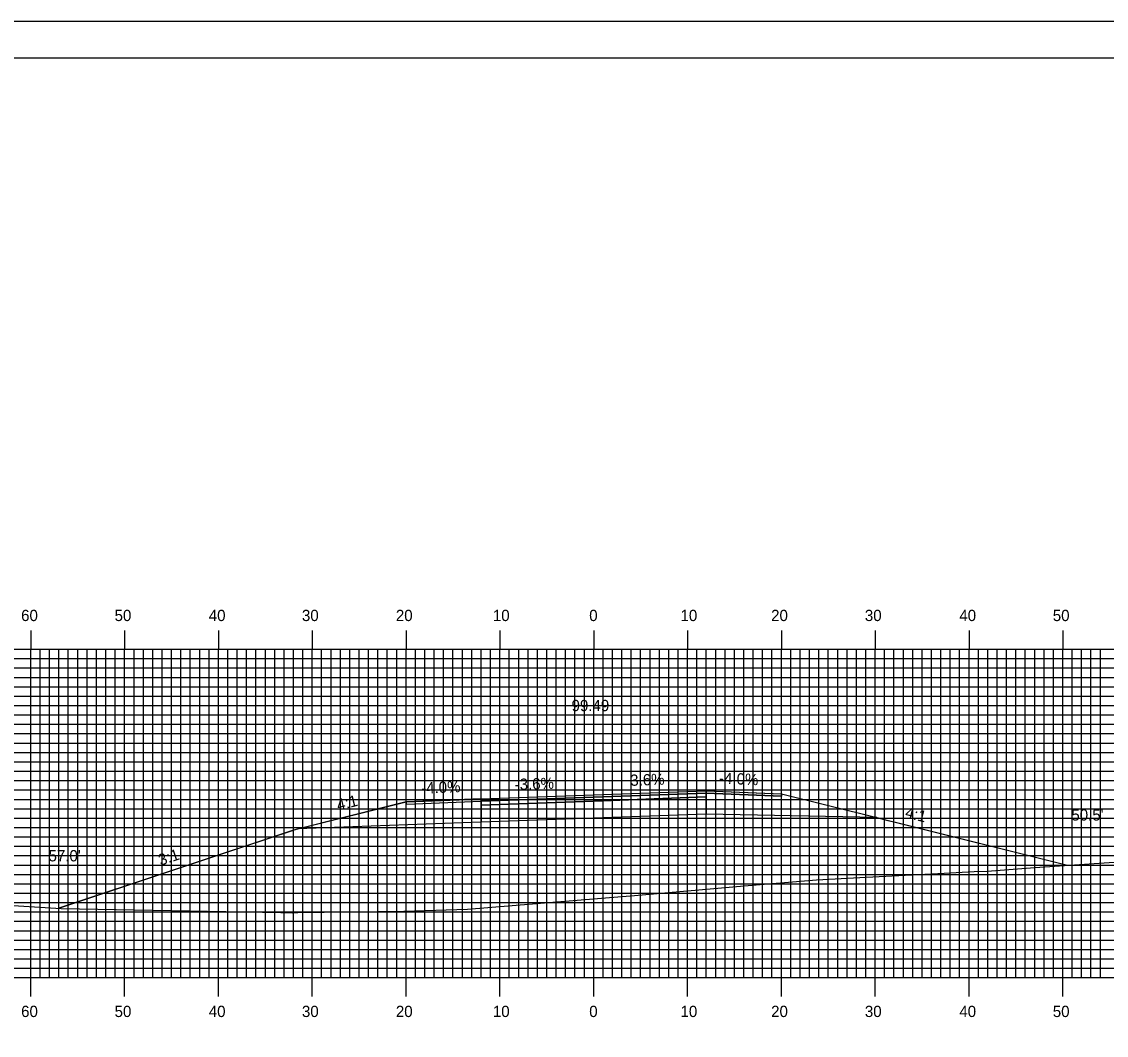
# Model space of a CAD drawing. Extents: x 1762972 to 1763315, y 442591 to 442811.
# Drawn here: x 1763076.3 to 1763191.9, y 442702.5 to 442810.5 of the extents above; entities that cross this region are included whole.
import ezdxf

# ---------------------------------------------------------------- set-up
doc = ezdxf.new("R2010")
doc.units = 0
for name, color, linetype in [('ANNOTATION', 7, 'Continuous'), ('BORDER', 7, 'Continuous'), ('D_Roadway_Centerline', 7, 'Continuous'), ('D_Roadway_Centerline_Text', 7, 'Continuous'), ('D_Roadway_Edge_Shoulder', 7, 'Continuous'), ('D_Roadway_Edge_TW', 7, 'Continuous'), ('D_Roadway_Pavement', 7, 'Continuous'), ('D_Roadway_SlopeLines', 7, 'Continuous'), ('D_Roadway_SubGrade', 7, 'Continuous'), ('D_Text_Standard', 7, 'Continuous'), ('H_V ANNOTATION', 7, 'Continuous'), ('MAJOR', 7, 'Continuous'), ('MINOR', 7, 'Continuous'), ('PLOT BOUNDARY', 7, 'Continuous'), ('S_Roadway_Centerline', 7, 'Continuous')]:
    doc.layers.add(name, color=color, linetype=linetype)

msp = doc.modelspace()

# ---------------------------------------------------------------- linework, layer by layer
at = {"layer": 'BORDER'}
msp.add_lwpolyline([(1762987.69, 442596.67), (1763307.69, 442596.67), (1763307.69, 442806.67), (1762987.69, 442806.67)], close=True, dxfattribs=at)
at = {"layer": 'D_Roadway_Centerline'}
msp.add_lwpolyline([(1763080.27, 442716.06), (1763100.01, 442722.64), (1763105.29, 442724.4), (1763105.35, 442724.42), (1763105.76, 442724.52), (1763112.1, 442726.11), (1763117.29, 442727.4), (1763122.93, 442727.63), (1763125.29, 442727.72), (1763125.29, 442727.72), (1763131.29, 442727.94), (1763137.29, 442728.16), (1763149.29, 442728.59), (1763149.29, 442728.59), (1763149.3, 442728.59), (1763156.38, 442728.3), (1763157.29, 442728.27), (1763167.47, 442725.72), (1763168.65, 442725.43), (1763169.29, 442725.27), (1763169.3, 442725.27), (1763187.78, 442720.65)], dxfattribs=at)
at = {"layer": 'D_Roadway_Edge_Shoulder'}
for points in [[(1763149.29, 442728.59), (1763157.29, 442728.27), (1763157.29, 442728.02), (1763149.29, 442728.34)], [(1763125.29, 442727.72), (1763117.29, 442727.4), (1763117.29, 442727.15), (1763125.29, 442727.47)]]:
    msp.add_lwpolyline(points, close=True, dxfattribs=at)
at = {"layer": 'D_Roadway_Edge_TW'}
for points in [[(1763125.29, 442727.47), (1763125.29, 442727.72), (1763137.29, 442728.16), (1763149.29, 442728.59), (1763149.29, 442728.34), (1763137.29, 442727.91)], [(1763149.29, 442728.59), (1763149.29, 442728.59), (1763149.29, 442728.34), (1763149.29, 442728.34)]]:
    msp.add_lwpolyline(points, close=True, dxfattribs=at)
at = {"layer": 'D_Roadway_Pavement'}
for points in [[(1763125.29, 442727.06), (1763125.29, 442727.47), (1763137.29, 442727.91), (1763149.29, 442728.34), (1763149.29, 442727.92), (1763137.29, 442727.49)], [(1763149.29, 442728.34), (1763149.29, 442728.34), (1763149.29, 442727.92), (1763149.29, 442727.92)]]:
    msp.add_lwpolyline(points, close=True, dxfattribs=at)
msp.add_lwpolyline([(1763149.29, 442728.34), (1763149.29, 442727.92)], dxfattribs=at)
msp.add_lwpolyline([(1763149.29, 442728.34), (1763149.29, 442727.92)], dxfattribs=at)
msp.add_lwpolyline([(1763149.29, 442728.34), (1763149.29, 442727.92)], dxfattribs=at)
at = {"layer": 'D_Roadway_SlopeLines'}
for points in [[(1763117.29, 442727.4), (1763105.29, 442724.4), (1763080.27, 442716.06)], [(1763157.29, 442728.27), (1763167.47, 442725.72), (1763169.29, 442725.27), (1763187.78, 442720.65)]]:
    msp.add_lwpolyline(points, dxfattribs=at)
at = {"layer": 'D_Roadway_SubGrade'}
for points in [[(1763117.29, 442727.15), (1763125.29, 442727.47), (1763125.29, 442727.06), (1763125.29, 442725.22), (1763105.76, 442724.52), (1763117.29, 442727.4)], [(1763125.29, 442725.22), (1763125.29, 442727.06), (1763137.29, 442727.49), (1763149.29, 442727.92), (1763149.29, 442726.09), (1763137.29, 442725.66)], [(1763149.29, 442727.92), (1763149.29, 442728.34), (1763157.29, 442728.02), (1763157.29, 442728.27), (1763167.47, 442725.72), (1763149.29, 442726.09)], [(1763149.29, 442727.92), (1763149.29, 442727.92), (1763149.29, 442726.09), (1763149.29, 442726.09)]]:
    msp.add_lwpolyline(points, close=True, dxfattribs=at)
at = {"layer": 'MAJOR'}
for p, q in [((1763077.29, 442745.67), (1763077.29, 442743.67)), ((1763087.29, 442745.67), (1763087.29, 442743.67)), ((1763097.29, 442745.67), (1763097.29, 442743.67)), ((1763107.29, 442745.67), (1763107.29, 442743.67)), ((1763117.29, 442745.67), (1763117.29, 442743.67)), ((1763127.29, 442745.67), (1763127.29, 442743.67)), ((1763137.29, 442745.67), (1763137.29, 442743.67)), ((1763147.29, 442745.67), (1763147.29, 442743.67)), ((1763157.29, 442745.67), (1763157.29, 442743.67)), ((1763167.29, 442745.67), (1763167.29, 442743.67)), ((1763177.29, 442745.67), (1763177.29, 442743.67)), ((1763187.29, 442745.67), (1763187.29, 442743.67)), ((1762997.29, 442743.67), (1763277.29, 442743.67)), ((1762997.29, 442743.67), (1763277.29, 442743.67)), ((1763077.29, 442708.67), (1763077.29, 442743.67)), ((1763087.29, 442708.67), (1763087.29, 442743.67)), ((1763097.29, 442708.67), (1763097.29, 442743.67)), ((1763107.29, 442708.67), (1763107.29, 442743.67)), ((1763117.29, 442708.67), (1763117.29, 442743.67)), ((1763127.29, 442708.67), (1763127.29, 442743.67)), ((1763137.29, 442708.67), (1763137.29, 442743.67)), ((1763147.29, 442708.67), (1763147.29, 442743.67)), ((1763157.29, 442708.67), (1763157.29, 442743.67)), ((1763167.29, 442708.67), (1763167.29, 442743.67)), ((1763177.29, 442708.67), (1763177.29, 442743.67)), ((1763187.29, 442708.67), (1763187.29, 442743.67)), ((1762997.29, 442738.67), (1763277.29, 442738.67)), ((1762997.29, 442733.67), (1763277.29, 442733.67)), ((1762997.29, 442728.67), (1763277.29, 442728.67)), ((1762997.29, 442723.67), (1763277.29, 442723.67)), ((1762997.29, 442718.67), (1763277.29, 442718.67)), ((1762997.29, 442713.67), (1763277.29, 442713.67)), ((1762997.29, 442708.67), (1763277.29, 442708.67)), ((1762997.29, 442708.67), (1763277.29, 442708.67)), ((1763077.29, 442706.66), (1763077.29, 442708.67)), ((1763087.29, 442706.66), (1763087.29, 442708.67)), ((1763097.29, 442706.66), (1763097.29, 442708.67)), ((1763107.29, 442706.66), (1763107.29, 442708.67)), ((1763117.29, 442706.66), (1763117.29, 442708.67)), ((1763127.29, 442706.66), (1763127.29, 442708.67)), ((1763137.29, 442706.66), (1763137.29, 442708.67)), ((1763147.29, 442706.66), (1763147.29, 442708.67)), ((1763157.29, 442706.66), (1763157.29, 442708.67)), ((1763167.29, 442706.66), (1763167.29, 442708.67)), ((1763177.29, 442706.66), (1763177.29, 442708.67)), ((1763187.29, 442706.66), (1763187.29, 442708.67))]:
    msp.add_line(p, q, dxfattribs=at)
at = {"layer": 'MINOR'}
for p, q in [((1763078.29, 442708.67), (1763078.29, 442743.67)), ((1763079.29, 442708.67), (1763079.29, 442743.67)), ((1763080.29, 442708.67), (1763080.29, 442743.67)), ((1763081.29, 442708.67), (1763081.29, 442743.67)), ((1763082.29, 442708.67), (1763082.29, 442743.67)), ((1763083.29, 442708.67), (1763083.29, 442743.67)), ((1763084.29, 442708.67), (1763084.29, 442743.67)), ((1763085.29, 442708.67), (1763085.29, 442743.67)), ((1763086.29, 442708.67), (1763086.29, 442743.67)), ((1763088.29, 442708.67), (1763088.29, 442743.67)), ((1763089.29, 442708.67), (1763089.29, 442743.67)), ((1763090.29, 442708.67), (1763090.29, 442743.67)), ((1763091.29, 442708.67), (1763091.29, 442743.67)), ((1763092.29, 442708.67), (1763092.29, 442743.67)), ((1763093.29, 442708.67), (1763093.29, 442743.67)), ((1763094.29, 442708.67), (1763094.29, 442743.67)), ((1763095.29, 442708.67), (1763095.29, 442743.67)), ((1763096.29, 442708.67), (1763096.29, 442743.67)), ((1763098.29, 442708.67), (1763098.29, 442743.67)), ((1763099.29, 442708.67), (1763099.29, 442743.67)), ((1763100.29, 442708.67), (1763100.29, 442743.67)), ((1763101.29, 442708.67), (1763101.29, 442743.67)), ((1763102.29, 442708.67), (1763102.29, 442743.67)), ((1763103.29, 442708.67), (1763103.29, 442743.67)), ((1763104.29, 442708.67), (1763104.29, 442743.67)), ((1763105.29, 442708.67), (1763105.29, 442743.67)), ((1763106.29, 442708.67), (1763106.29, 442743.67)), ((1763108.29, 442708.67), (1763108.29, 442743.67)), ((1763109.29, 442708.67), (1763109.29, 442743.67)), ((1763110.29, 442708.67), (1763110.29, 442743.67)), ((1763111.29, 442708.67), (1763111.29, 442743.67)), ((1763112.29, 442708.67), (1763112.29, 442743.67)), ((1763113.29, 442708.67), (1763113.29, 442743.67)), ((1763114.29, 442708.67), (1763114.29, 442743.67)), ((1763115.29, 442708.67), (1763115.29, 442743.67)), ((1763116.29, 442708.67), (1763116.29, 442743.67)), ((1763118.29, 442708.67), (1763118.29, 442743.67)), ((1763119.29, 442708.67), (1763119.29, 442743.67)), ((1763120.29, 442708.67), (1763120.29, 442743.67)), ((1763121.29, 442708.67), (1763121.29, 442743.67)), ((1763122.29, 442708.67), (1763122.29, 442743.67)), ((1763123.29, 442708.67), (1763123.29, 442743.67)), ((1763124.29, 442708.67), (1763124.29, 442743.67)), ((1763125.29, 442708.67), (1763125.29, 442743.67)), ((1763126.29, 442708.67), (1763126.29, 442743.67)), ((1763128.29, 442708.67), (1763128.29, 442743.67)), ((1763129.29, 442708.67), (1763129.29, 442743.67)), ((1763130.29, 442708.67), (1763130.29, 442743.67)), ((1763131.29, 442708.67), (1763131.29, 442743.67)), ((1763132.29, 442708.67), (1763132.29, 442743.67)), ((1763133.29, 442708.67), (1763133.29, 442743.67)), ((1763134.29, 442708.67), (1763134.29, 442743.67)), ((1763135.29, 442708.67), (1763135.29, 442743.67)), ((1763136.29, 442708.67), (1763136.29, 442743.67)), ((1763138.29, 442708.67), (1763138.29, 442743.67)), ((1763139.29, 442708.67), (1763139.29, 442743.67)), ((1763140.29, 442708.67), (1763140.29, 442743.67)), ((1763141.29, 442708.67), (1763141.29, 442743.67)), ((1763142.29, 442708.67), (1763142.29, 442743.67)), ((1763143.29, 442708.67), (1763143.29, 442743.67)), ((1763144.29, 442708.67), (1763144.29, 442743.67)), ((1763145.29, 442708.67), (1763145.29, 442743.67)), ((1763146.29, 442708.67), (1763146.29, 442743.67)), ((1763148.29, 442708.67), (1763148.29, 442743.67)), ((1763149.29, 442708.67), (1763149.29, 442743.67)), ((1763150.29, 442708.67), (1763150.29, 442743.67)), ((1763151.29, 442708.67), (1763151.29, 442743.67)), ((1763152.29, 442708.67), (1763152.29, 442743.67)), ((1763153.29, 442708.67), (1763153.29, 442743.67)), ((1763154.29, 442708.67), (1763154.29, 442743.67)), ((1763155.29, 442708.67), (1763155.29, 442743.67)), ((1763156.29, 442708.67), (1763156.29, 442743.67)), ((1763158.29, 442708.67), (1763158.29, 442743.67)), ((1763159.29, 442708.67), (1763159.29, 442743.67)), ((1763160.29, 442708.67), (1763160.29, 442743.67)), ((1763161.29, 442708.67), (1763161.29, 442743.67)), ((1763162.29, 442708.67), (1763162.29, 442743.67)), ((1763163.29, 442708.67), (1763163.29, 442743.67)), ((1763164.29, 442708.67), (1763164.29, 442743.67)), ((1763165.29, 442708.67), (1763165.29, 442743.67)), ((1763166.29, 442708.67), (1763166.29, 442743.67)), ((1763168.29, 442708.67), (1763168.29, 442743.67)), ((1763169.29, 442708.67), (1763169.29, 442743.67)), ((1763170.29, 442708.67), (1763170.29, 442743.67)), ((1763171.29, 442708.67), (1763171.29, 442743.67)), ((1763172.29, 442708.67), (1763172.29, 442743.67)), ((1763173.29, 442708.67), (1763173.29, 442743.67)), ((1763174.29, 442708.67), (1763174.29, 442743.67)), ((1763175.29, 442708.67), (1763175.29, 442743.67)), ((1763176.29, 442708.67), (1763176.29, 442743.67)), ((1763178.29, 442708.67), (1763178.29, 442743.67)), ((1763179.29, 442708.67), (1763179.29, 442743.67)), ((1763180.29, 442708.67), (1763180.29, 442743.67)), ((1763181.29, 442708.67), (1763181.29, 442743.67)), ((1763182.29, 442708.67), (1763182.29, 442743.67)), ((1763183.29, 442708.67), (1763183.29, 442743.67)), ((1763184.29, 442708.67), (1763184.29, 442743.67)), ((1763185.29, 442708.67), (1763185.29, 442743.67)), ((1763186.29, 442708.67), (1763186.29, 442743.67)), ((1763188.29, 442708.67), (1763188.29, 442743.67)), ((1763189.29, 442708.67), (1763189.29, 442743.67)), ((1763190.29, 442708.67), (1763190.29, 442743.67)), ((1763191.29, 442708.67), (1763191.29, 442743.67)), ((1762997.29, 442742.67), (1763277.29, 442742.67)), ((1762997.29, 442741.67), (1763277.29, 442741.67)), ((1762997.29, 442740.67), (1763277.29, 442740.67)), ((1762997.29, 442739.67), (1763277.29, 442739.67)), ((1762997.29, 442737.67), (1763277.29, 442737.67)), ((1762997.29, 442736.67), (1763277.29, 442736.67)), ((1762997.29, 442735.67), (1763277.29, 442735.67)), ((1762997.29, 442734.67), (1763277.29, 442734.67)), ((1762997.29, 442732.67), (1763277.29, 442732.67)), ((1762997.29, 442731.67), (1763277.29, 442731.67)), ((1762997.29, 442730.67), (1763277.29, 442730.67)), ((1762997.29, 442729.67), (1763277.29, 442729.67)), ((1762997.29, 442727.67), (1763277.29, 442727.67)), ((1762997.29, 442726.67), (1763277.29, 442726.67)), ((1762997.29, 442725.67), (1763277.29, 442725.67)), ((1762997.29, 442724.67), (1763277.29, 442724.67)), ((1762997.29, 442722.67), (1763277.29, 442722.67)), ((1762997.29, 442721.67), (1763277.29, 442721.67)), ((1762997.29, 442720.67), (1763277.29, 442720.67)), ((1762997.29, 442719.67), (1763277.29, 442719.67)), ((1762997.29, 442717.67), (1763277.29, 442717.67)), ((1762997.29, 442716.67), (1763277.29, 442716.67)), ((1762997.29, 442715.67), (1763277.29, 442715.67)), ((1762997.29, 442714.67), (1763277.29, 442714.67)), ((1762997.29, 442712.67), (1763277.29, 442712.67)), ((1762997.29, 442711.67), (1763277.29, 442711.67)), ((1762997.29, 442710.67), (1763277.29, 442710.67)), ((1762997.29, 442709.67), (1763277.29, 442709.67))]:
    msp.add_line(p, q, dxfattribs=at)
at = {"layer": 'PLOT BOUNDARY'}
msp.add_lwpolyline([(1762971.51, 442590.55), (1763311.51, 442590.55), (1763311.51, 442810.55), (1762971.51, 442810.55)], close=True, dxfattribs=at)
at = {"layer": 'S_Roadway_Centerline'}
msp.add_lwpolyline([(1763069.72, 442716.7), (1763080.53, 442716.05), (1763103.93, 442715.62), (1763105.16, 442715.59), (1763105.74, 442715.6), (1763117.05, 442715.77), (1763123.85, 442715.98), (1763140.29, 442717.3), (1763141.65, 442717.41), (1763153.32, 442718.46), (1763161.05, 442719.1), (1763165.67, 442719.34), (1763174.63, 442719.79), (1763177.84, 442719.97), (1763179.24, 442720.02), (1763184.32, 442720.42), (1763198.54, 442721.35)], dxfattribs=at)

# ---------------------------------------------------------------- texts
at = {"layer": 'ANNOTATION'}
for s, rotation, p in [('-4.0%', 2.2904, (1763118.92, 442728.27)), ('-3.6%', 2.0618, (1763128.88, 442728.65)), ('3.6%', 2.0619, (1763141.2, 442729.1)), ('-4.0%', 357.7096, (1763150.63, 442729.34)), ('4:1', 14.0402, (1763110.06, 442726.46)), ('4:1', 345.9626, (1763170.41, 442725.75)), ('3:1', 18.4355, (1763091.12, 442720.59))]:
    msp.add_text(s, height=1.2, rotation=rotation, dxfattribs=at).set_placement(p)
at = {"layer": 'D_Roadway_Centerline'}
for s, p in [('C', (1763137.29, 442728.16)), ('L', (1763137.29, 442728.15))]:
    msp.add_text(s, height=0.0146, dxfattribs=at).set_placement(p)
at = {"layer": 'D_Roadway_Centerline_Text'}
msp.add_text('99.49', height=1.2, dxfattribs=at).set_placement((1763134.93, 442737.07))
at = {"layer": 'D_Text_Standard'}
for s, p in [("50.5'", (1763188.2, 442725.41)), ("57.0'", (1763079.18, 442721.06))]:
    msp.add_text(s, height=1.2, dxfattribs=at).set_placement(p)
at = {"layer": 'H_V ANNOTATION'}
for s, p in [('60', (1763076.26, 442746.67)), ('50', (1763086.22, 442746.67)), ('40', (1763096.26, 442746.67)), ('30', (1763106.19, 442746.67)), ('20', (1763116.2, 442746.67)), ('10', (1763126.54, 442746.67)), ('0', (1763136.81, 442746.67)), ('10', (1763146.54, 442746.67)), ('20', (1763156.2, 442746.67)), ('30', (1763166.19, 442746.67)), ('40', (1763176.26, 442746.67)), ('50', (1763186.22, 442746.67)), ('60', (1763076.26, 442704.47)), ('50', (1763086.22, 442704.47)), ('40', (1763096.26, 442704.47)), ('30', (1763106.19, 442704.47)), ('20', (1763116.2, 442704.47)), ('10', (1763126.54, 442704.47)), ('0', (1763136.81, 442704.47)), ('10', (1763146.54, 442704.47)), ('20', (1763156.2, 442704.47)), ('30', (1763166.19, 442704.47)), ('40', (1763176.26, 442704.47)), ('50', (1763186.22, 442704.47))]:
    msp.add_text(s, height=1.2, dxfattribs=at).set_placement(p)

doc.saveas('drawing.dxf')
